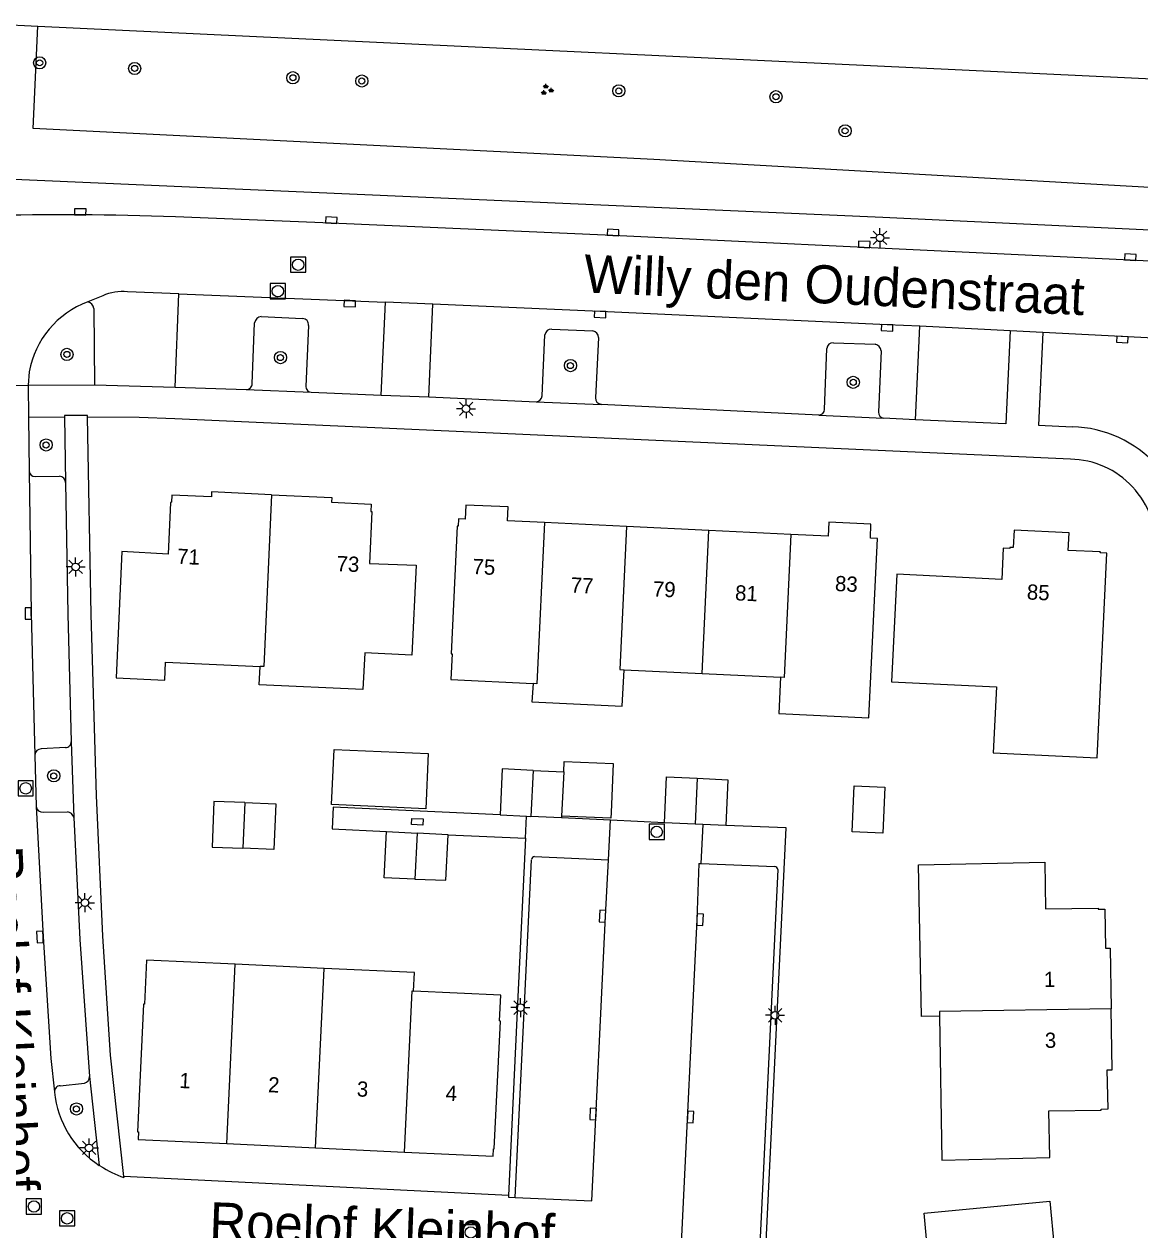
# Model space of a CAD drawing. Extents: x 132994 to 136000, y 393499 to 395512.
# Drawn here: x 133042.5 to 133115.7, y 394512.1 to 394591.2 of the extents above; entities that cross this region are included whole.
import ezdxf

# ---------------------------------------------------------------- set-up
doc = ezdxf.new("R2010")
doc.units = 0
for name, color, linetype in [('gg-afsc-hekwerk', 7, 'Continuous'), ('gg-anno-huisnummerreeks BGT', 7, 'Continuous'), ('gg-anno-openbare ruimte label', 7, 'Continuous'), ('gg-bbg-bijgebouw', 7, 'Continuous'), ('gg-bbg-hoofdgebouw', 7, 'Continuous'), ('gg-bbg-luifel en loopbrug', 7, 'Continuous'), ('gg-bbg-tussenscheiding', 7, 'Continuous'), ('gg-knt-verharding', 7, 'Continuous'), ('gg-knt-verharding nz', 7, 'Continuous'), ('gt-grn-groengrens', 7, 'Continuous'), ('gt-grn-weggrens', 7, 'Continuous'), ('gt-symb-boom', 7, 'Continuous'), ('gt-symb-groenvak', 7, 'Continuous'), ('gt-symb-kolk', 7, 'Continuous'), ('gt-symb-kolk center center', 7, 'Continuous'), ('gt-symb-lichtmast', 7, 'Continuous'), ('gt-symb-rioolschacht', 7, 'Continuous')]:
    doc.layers.add(name, color=color, linetype=linetype)

# ---------------------------------------------------------------- blocks, each defined once
blk = doc.blocks.new('gt0-BOOM')
at = {"layer": 'gt-symb-boom'}
for radius in [0.4, 0.2]:
    blk.add_circle((0, 0), radius, dxfattribs=at)
blk = doc.blocks.new('gt0-LMAST')
at = {"layer": 'gt-symb-lichtmast'}
for p, q in [((-0.182, 0.173), (-0.447, 0.438)), ((-0.005, 0.246), (-0.005, 0.621)), ((0.172, 0.173), (0.437, 0.438)), ((-0.255, -0.004), (-0.63, -0.004)), ((-0.182, -0.181), (-0.447, -0.446)), ((-0.005, -0.254), (-0.005, -0.629)), ((0.437, -0.446), (0.172, -0.181)), ((0.245, -0.004), (0.62, -0.004))]:
    blk.add_line(p, q, dxfattribs=at)
blk.add_circle((-0.005, -0.004), 0.25, dxfattribs=at)
blk = doc.blocks.new('gt0-KOLKCC')
at = {"layer": 'gt-symb-kolk center center'}
blk.add_lwpolyline([(-0.375, 0.2), (0.375, 0.2), (0.375, -0.2), (-0.375, -0.2)], close=True, dxfattribs=at)
blk = doc.blocks.new('gt0-KOLK')
at = {"layer": 'gt-symb-kolk'}
blk.add_lwpolyline([(0, 0), (0.375, 0), (0.375, 0.4), (-0.375, 0.4), (-0.375, 0), (0, 0)], dxfattribs=at)
blk = doc.blocks.new('gt0-RS')
at = {"layer": 'gt-symb-rioolschacht'}
blk.add_lwpolyline([(-0.5, -0.5), (0.5, -0.5), (0.5, 0.5), (-0.5, 0.5)], close=True, dxfattribs=at)
blk.add_circle((0, 0), 0.375, dxfattribs=at)
blk = doc.blocks.new('gt0-GRVAK')
at = {"layer": 'gt-symb-groenvak'}
for p, q in [((-0.11, 0.189), (-0.228, 0.24)), ((-0.182, 0.153), (0.088, 0.153)), ((-0.091, 0.211), (-0.156, 0.322)), ((-0.047, 0.214), (-0.047, 0.393)), ((-0.004, 0.211), (0.061, 0.322)), ((0.015, 0.189), (0.133, 0.24)), ((0.262, -0.052), (0.197, 0.059)), ((0.305, -0.049), (0.305, 0.13)), ((0.349, -0.052), (0.414, 0.059)), ((-0.245, -0.228), (-0.363, -0.177)), ((-0.318, -0.264), (-0.047, -0.264)), ((-0.226, -0.206), (-0.291, -0.095)), ((-0.183, -0.203), (-0.183, -0.024)), ((-0.139, -0.206), (-0.074, -0.095)), ((-0.12, -0.228), (-0.002, -0.177)), ((0.243, -0.074), (0.125, -0.023)), ((0.17, -0.11), (0.441, -0.11)), ((0.368, -0.074), (0.486, -0.023))]:
    blk.add_line(p, q, dxfattribs=at)

msp = doc.modelspace()

# ---------------------------------------------------------------- linework, layer by layer
at = {"layer": 'gg-afsc-hekwerk'}
for p, q in [((133040.64, 394591.221), (133043.422, 394591.089)), ((133043.422, 394591.089), (133124.891, 394587.234)), ((133080.997, 394538.954), (133077.791, 394539.109)), ((133084.542, 394538.783), (133080.997, 394538.954)), ((133070.341, 394538.004), (133075.419, 394537.769)), ((133075.419, 394537.769), (133074.923, 394527.362))]:
    msp.add_line(p, q, dxfattribs=at)
for points in [[(133073.754, 394539.304), (133062.812, 394539.814), (133062.74, 394538.389), (133066.303, 394538.209)], [(133091.083, 394508.56), (133092.539, 394538.454), (133088.577, 394538.6)]]:
    msp.add_lwpolyline(points, dxfattribs=at)
at = {"layer": 'gg-bbg-bijgebouw'}
for p, q in [((133075.919, 394542.223), (133077.937, 394542.125)), ((133077.937, 394542.125), (133077.797, 394539.227)), ((133073.754, 394539.304), (133075.488, 394539.221)), ((133075.488, 394539.221), (133075.772, 394539.207)), ((133077.791, 394539.109), (133075.772, 394539.207)), ((133077.797, 394539.227), (133077.791, 394539.109)), ((133086.559, 394538.692), (133084.542, 394538.783)), ((133087.068, 394538.669), (133086.559, 394538.692)), ((133088.577, 394538.6), (133087.068, 394538.669)), ((133066.303, 394538.209), (133068.322, 394538.107)), ((133070.341, 394538.004), (133068.322, 394538.107))]:
    msp.add_line(p, q, dxfattribs=at)
for points in [[(133075.919, 394542.223), (133073.9, 394542.32), (133073.754, 394539.304)], [(133084.542, 394538.783), (133084.679, 394541.799), (133086.696, 394541.708)], [(133086.696, 394541.708), (133088.714, 394541.616), (133088.577, 394538.6)], [(133098.877, 394538.094), (133096.857, 394538.189), (133096.998, 394541.216), (133099.019, 394541.121), (133098.877, 394538.094)], [(133057.007, 394540.11), (133054.968, 394540.185), (133054.857, 394537.191), (133056.88, 394537.116)], [(133057.007, 394540.11), (133059.046, 394540.034), (133058.903, 394537.041), (133056.88, 394537.116)], [(133068.169, 394535.091), (133066.149, 394535.17), (133066.303, 394538.209)], [(133068.169, 394535.091), (133070.189, 394535.012), (133070.341, 394538.004)]]:
    msp.add_lwpolyline(points, dxfattribs=at)
at = {"layer": 'gg-bbg-hoofdgebouw'}
for p, q in [((133082.061, 394558.237), (133076.667, 394558.493)), ((133087.454, 394557.98), (133082.061, 394558.237)), ((133092.848, 394557.724), (133087.454, 394557.98)), ((133081.894, 394548.838), (133087.01, 394548.59)), ((133087.01, 394548.59), (133092.163, 394548.341)), ((133062.208, 394529.225), (133056.381, 394529.499)), ((133055.821, 394517.725), (133061.647, 394517.448)), ((133061.647, 394517.448), (133067.474, 394517.17))]:
    msp.add_line(p, q, dxfattribs=at)
for points in [[(133058.756, 394560.328), (133054.825, 394560.505), (133054.816, 394560.193), (133052.218, 394560.306), (133052.194, 394559.827), (133052.131, 394559.824), (133051.969, 394556.43), (133048.926, 394556.59), (133048.552, 394548.313), (133051.746, 394548.146), (133051.804, 394549.333), (133058.009, 394549.055)], [(133058.756, 394560.328), (133062.719, 394560.149), (133062.699, 394559.834), (133065.304, 394559.709), (133065.281, 394559.225), (133065.344, 394559.22), (133065.194, 394555.812), (133068.242, 394555.694), (133067.974, 394549.794), (133064.876, 394549.94), (133064.759, 394547.537), (133057.954, 394547.844), (133058.009, 394549.055)], [(133076.667, 394558.493), (133074.248, 394558.608), (133074.287, 394559.524), (133071.517, 394559.643), (133071.473, 394558.721), (133071.031, 394558.751), (133071.008, 394558.265), (133070.938, 394558.268), (133070.544, 394549.875), (133070.606, 394549.87), (133070.522, 394548.185), (133075.923, 394547.925)], [(133097.954, 394545.667), (133098.519, 394557.445), (133098.06, 394557.469), (133098.097, 394558.396), (133095.324, 394558.528), (133095.28, 394557.608), (133092.848, 394557.724)], [(133099.456, 394548.043), (133106.333, 394547.703), (133106.12, 394543.372), (133112.936, 394543.047), (133113.581, 394556.493), (133113.149, 394556.514), (133113.152, 394556.574), (133111.047, 394556.67), (133111.101, 394557.824), (133107.496, 394557.993), (133107.436, 394556.852), (133107.211, 394556.864), (133107.207, 394556.796), (133106.778, 394556.813), (133106.682, 394554.765), (133099.792, 394555.101), (133099.456, 394548.043)], [(133075.923, 394547.925), (133075.849, 394546.73), (133081.776, 394546.438), (133081.894, 394548.838)], [(133092.163, 394548.341), (133092.041, 394545.967), (133097.954, 394545.667)], [(133102.604, 394526.086), (133101.406, 394526.079), (133101.218, 394536.032), (133109.506, 394536.203), (133109.547, 394533.137), (133113.015, 394533.171), (133113.016, 394533.111), (133113.456, 394533.115), (133113.481, 394530.56), (133113.805, 394530.565), (133113.867, 394526.569)], [(133056.381, 394529.499), (133050.558, 394529.772), (133050.421, 394526.879), (133050.358, 394526.879), (133049.958, 394518.498), (133050.02, 394518.495), (133049.994, 394518.002), (133055.821, 394517.725)], [(133068.073, 394527.738), (133068.13, 394528.947), (133062.208, 394529.225)], [(133067.474, 394517.17), (133073.301, 394516.893), (133073.321, 394517.383), (133073.378, 394517.38), (133073.785, 394525.767), (133073.728, 394525.78), (133073.796, 394527.464), (133068.073, 394527.738)], [(133102.604, 394526.086), (133102.755, 394516.647), (133109.84, 394516.801), (133109.765, 394519.867), (133113.216, 394519.928), (133113.215, 394519.988), (133113.655, 394519.996), (133113.609, 394522.568), (133113.929, 394522.573), (133113.867, 394526.569)], [(133102.452, 394503.775), (133101.59, 394513.164), (133109.841, 394513.947), (133110.125, 394510.923), (133113.553, 394511.195), (133113.558, 394511.135), (133113.99, 394511.169), (133114.237, 394508.634), (133114.548, 394508.66), (133114.847, 394504.714)]]:
    msp.add_lwpolyline(points, dxfattribs=at)
at = {"layer": 'gg-bbg-luifel en loopbrug'}
for points in [[(133062.697, 394539.982), (133062.861, 394543.605), (133069.043, 394543.326), (133068.879, 394539.704), (133062.697, 394539.982)], [(133077.937, 394542.125), (133077.968, 394542.813), (133081.183, 394542.668), (133081.038, 394539.452), (133081.021, 394539.081), (133077.797, 394539.227)]]:
    msp.add_lwpolyline(points, dxfattribs=at)
at = {"layer": 'gg-bbg-tussenscheiding'}
for p, q in [((133087.01, 394548.59), (133087.454, 394557.98)), ((133075.919, 394542.223), (133075.772, 394539.207)), ((133086.696, 394541.708), (133086.559, 394538.692)), ((133057.007, 394540.11), (133056.88, 394537.116)), ((133068.322, 394538.107), (133068.169, 394535.091)), ((133055.821, 394517.725), (133056.381, 394529.499)), ((133061.647, 394517.448), (133062.208, 394529.225))]:
    msp.add_line(p, q, dxfattribs=at)
for points in [[(133058.756, 394560.328), (133058.244, 394549.044), (133058.009, 394549.055)], [(133076.667, 394558.493), (133076.166, 394547.914), (133075.923, 394547.925)], [(133082.061, 394558.237), (133081.616, 394548.851), (133081.894, 394548.838)], [(133092.848, 394557.724), (133092.404, 394548.33), (133092.163, 394548.341)], [(133067.474, 394517.17), (133067.977, 394527.743), (133068.073, 394527.738)], [(133113.867, 394526.569), (133102.599, 394526.394), (133102.604, 394526.086)]]:
    msp.add_lwpolyline(points, dxfattribs=at)
at = {"layer": 'gg-knt-verharding'}
for p, q in [((133047.105, 394572.541), (133047.133, 394567.545)), ((133058.083, 394572.018), (133060.795, 394571.893)), ((133057.487, 394567.615), (133057.643, 394571.612)), ((133061.183, 394571.438), (133061.004, 394567.435)), ((133077.151, 394571.197), (133079.841, 394571.074)), ((133109.377, 394570.984), (133107.239, 394571.092)), ((133076.52, 394566.817), (133076.703, 394570.824)), ((133080.207, 394570.641), (133080.025, 394566.685)), ((133095.631, 394570.303), (133098.367, 394570.202)), ((133119.093, 394570.489), (133109.377, 394570.984)), ((133095.058, 394565.927), (133095.194, 394569.934)), ((133098.766, 394569.772), (133098.585, 394565.751)), ((133042.86, 394568.386), (133042.78, 394567.522)), ((133042.78, 394567.522), (133047.133, 394567.545)), ((133042.78, 394567.522), (133042.803, 394565.416)), ((133047.133, 394567.545), (133052.432, 394567.393)), ((133052.432, 394567.393), (133057.094, 394567.228)), ((133057.094, 394567.228), (133061.368, 394567.051)), ((133061.368, 394567.051), (133065.963, 394566.86)), ((133065.963, 394566.86), (133069.073, 394566.754)), ((133069.073, 394566.754), (133076.119, 394566.432)), ((133076.119, 394566.432), (133080.38, 394566.258)), ((133094.67, 394565.558), (133080.38, 394566.258)), ((133094.67, 394565.558), (133098.916, 394565.358)), ((133042.803, 394565.416), (133045.176, 394565.428)), ((133042.803, 394565.416), (133042.846, 394561.87)), ((133045.176, 394565.428), (133045.238, 394561.121)), ((133101.01, 394565.25), (133098.916, 394565.358)), ((133043.247, 394561.52), (133044.842, 394561.544)), ((133045.616, 394544.111), (133045.774, 394539.134)), ((133045.234, 394543.726), (133043.646, 394543.637)), ((133043.231, 394543.235), (133043.303, 394539.86)), ((133043.777, 394539.473), (133045.363, 394539.505)), ((133074.738, 394514.19), (133075.821, 394536.365)), ((133076.019, 394536.566), (133080.871, 394536.348)), ((133086.809, 394536.118), (133086.939, 394536.113)), ((133086.939, 394536.113), (133091.792, 394535.919)), ((133091.98, 394535.722), (133090.794, 394511.096)), ((133074.923, 394527.362), (133074.305, 394514.325)), ((133046.803, 394522.126), (133047.455, 394516.297)), ((133044.886, 394521.522), (133046.476, 394521.697)), ((133047.542, 394516.242), (133047.455, 394516.297)), ((133074.305, 394514.325), (133049.062, 394515.569))]:
    msp.add_line(p, q, dxfattribs=at)
for points in [[(133000.84, 394582.282), (133008.833, 394582.314), (133014.845, 394582.146), (133022.858, 394581.865), (133098.874, 394578.557), (133182.516, 394574.595)], [(133119.344, 394575.497), (133115.103, 394575.72), (133097.644, 394576.559), (133081.165, 394577.337), (133062.671, 394578.155), (133052.445, 394578.565)], [(133107.239, 394571.092), (133106.941, 394564.978), (133101.01, 394565.25)], [(133109.377, 394570.984), (133109.101, 394564.895), (133111.325, 394564.791)], [(133046.676, 394565.409), (133046.676, 394565.524), (133045.177, 394565.526), (133045.176, 394565.428)], [(133111.193, 394562.657), (133052.415, 394565.305), (133050.071, 394565.396), (133046.676, 394565.409)], [(133049.062, 394515.569), (133048.19, 394523.532), (133047.687, 394531.332), (133047.262, 394540.581), (133046.91, 394552.47), (133046.676, 394565.409)], [(133045.238, 394561.121), (133045.398, 394552.478), (133045.616, 394544.111)], [(133045.774, 394539.134), (133046.17, 394531.129), (133046.803, 394522.126)], [(133074.305, 394514.325), (133074.299, 394514.199), (133074.738, 394514.19)]]:
    msp.add_lwpolyline(points, dxfattribs=at)
for centre, radius, start, end in [((133044.971, 394371.221), 207.479, 87.93568, 91.3854), ((133048.759, 394567.364), 5.987, 110.19838, 170.17331), ((133046.588, 394572.472), 0.521, 7.60664, 78.50812), ((133058.114, 394571.543), 0.476, 93.68455, 171.71259), ((133060.789, 394571.495), 0.398, 351.80749, 89.1041), ((133077.116, 394570.784), 0.415, 85.12234, 174.43846), ((133079.793, 394570.662), 0.415, 357.1034, 83.30997), ((133095.613, 394569.881), 0.423, 87.59221, 172.76285), ((133098.305, 394569.745), 0.462, 3.40842, 82.30848), ((133057.103, 394567.612), 0.384, 268.69355, 0.425), ((133061.389, 394567.435), 0.385, 180.00062, 266.93616), ((133076.096, 394566.857), 0.426, 273.0831, 354.58457), ((133080.418, 394566.651), 0.394, 174.99794, 264.4811), ((133094.676, 394565.941), 0.383, 269.14848, 357.97598), ((133098.957, 394565.728), 0.372, 176.45764, 263.75315), ((133111.079, 394556.926), 7.869, 356.86028, 88.20813), ((133111.097, 394556.965), 5.693, 356.61691, 89.03435), ((133043.228, 394561.903), 0.384, 185.00433, 272.76559), ((133044.791, 394561.099), 0.448, 2.77867, 83.44495), ((133045.234, 394544.108), 0.382, 270.05877, 0.38943), ((133043.641, 394543.227), 0.41, 89.2452, 178.93158), ((133043.755, 394539.93), 0.457, 188.78565, 272.75412), ((133045.323, 394539.047), 0.459, 10.86472, 84.99164), ((133076.032, 394536.356), 0.211, 93.43238, 177.4292), ((133091.765, 394535.705), 0.215, 4.42396, 82.89777), ((133046.405, 394522.09), 0.399, 280.17715, 5.19081), ((133044.893, 394521.147), 0.375, 91.02328, 185.31187), ((133050.964, 394521.739), 6.476, 185.56031, 237.18612)]:
    msp.add_arc(centre, radius, start, end, dxfattribs=at)
at = {"layer": 'gg-knt-verharding nz'}
for p, q in [((133047.676, 394573.392), (133046.692, 394572.983)), ((133052.673, 394573.517), (133049.296, 394573.65)), ((133052.432, 394567.393), (133052.673, 394573.517)), ((133052.673, 394573.517), (133066.229, 394572.974)), ((133065.963, 394566.86), (133066.229, 394572.974)), ((133069.338, 394572.839), (133066.229, 394572.974)), ((133069.073, 394566.754), (133069.338, 394572.839)), ((133101.01, 394565.25), (133101.308, 394571.381)), ((133107.239, 394571.092), (133101.308, 394571.381)), ((133080.871, 394536.348), (133080.997, 394538.954)), ((133087.068, 394538.669), (133086.939, 394536.113)), ((133049.062, 394515.569), (133049.069, 394515.502))]:
    msp.add_line(p, q, dxfattribs=at)
for points in [[(133101.308, 394571.381), (133099.167, 394571.486), (133080.331, 394572.36), (133069.338, 394572.839)], [(133042.846, 394561.87), (133042.988, 394552.534), (133043.231, 394543.235)], [(133043.303, 394539.86), (133043.759, 394531.293), (133044.274, 394523.316), (133044.519, 394521.112)], [(133074.738, 394514.19), (133079.789, 394513.958), (133080.679, 394532.647), (133080.871, 394536.348)], [(133086.809, 394536.118), (133086.68, 394532.441), (133085.652, 394511.16)]]:
    msp.add_lwpolyline(points, dxfattribs=at)
for centre, radius, start, end in [((133048.964, 394570.517), 3.15, 83.95623, 114.14155), ((133050.961, 394521.352), 6.149, 236.21362, 252.07577)]:
    msp.add_arc(centre, radius, start, end, dxfattribs=at)
at = {"layer": 'gt-grn-groengrens'}
msp.add_line((133043.103, 394584.359), (133043.422, 394591.089), dxfattribs=at)
msp.add_lwpolyline([(133124.891, 394587.234), (133124.545, 394580.037), (133083.855, 394582.336), (133043.103, 394584.359)], dxfattribs=at)
at = {"layer": 'gt-grn-weggrens'}
for p, q in [((133037.827, 394567.391), (133042.78, 394567.522)), ((133075.419, 394537.769), (133075.488, 394539.221))]:
    msp.add_line(p, q, dxfattribs=at)

# ---------------------------------------------------------------- block references
at = {"layer": 'gt-symb-boom'}
for p in [(133043.54, 394588.679), (133049.774, 394588.309), (133060.161, 394587.7), (133064.682, 394587.486), (133081.549, 394586.836), (133091.864, 394586.454), (133096.399, 394584.214), (133045.33, 394569.536), (133059.342, 394569.327), (133078.376, 394568.801), (133096.936, 394567.704), (133043.963, 394563.592), (133044.463, 394541.865), (133045.952, 394519.999)]:
    msp.add_blockref('gt0-BOOM', p, dxfattribs=at)
at = {"layer": 'gt-symb-groenvak'}
msp.add_blockref('gt0-GRVAK', (133076.809, 394586.898), dxfattribs=at)
at = {"layer": 'gt-symb-kolk'}
for p, rotation in [((133046.197, 394578.696), -1.2025665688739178), ((133062.671, 394578.155), -3.003456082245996), ((133081.165, 394577.337), -3.0034560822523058), ((133097.644, 394576.559), -3.0034560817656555), ((133115.103, 394575.72), -3.003456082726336), ((133063.898, 394573.076), 177.74809154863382), ((133080.331, 394572.36), 177.5055394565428), ((133099.167, 394571.486), 177.34393590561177), ((133114.609, 394570.719), 177.09366989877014), ((133042.988, 394552.534), 90.87159696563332), ((133080.679, 394532.647), 87.02072152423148), ((133086.68, 394532.441), -92.76891578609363), ((133043.759, 394531.293), 93.0518080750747), ((133080.061, 394519.659), 87.27944664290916), ((133086.054, 394519.487), -92.76891578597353)]:
    msp.add_blockref('gt0-KOLK', p, dxfattribs=dict(at, rotation=rotation))
at = {"layer": 'gt-symb-kolk center center', "rotation": -2.429615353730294}
msp.add_blockref('gt0-KOLKCC', (133068.331, 394538.854), dxfattribs=at)
at = {"layer": 'gt-symb-lichtmast'}
for p in [(133098.692, 394577.193), (133071.532, 394565.972), (133045.903, 394555.59), (133046.51, 394533.544), (133075.1, 394526.653), (133091.811, 394526.15), (133046.79, 394517.446)]:
    msp.add_blockref('gt0-LMAST', p, dxfattribs=at)
at = {"layer": 'gt-symb-rioolschacht'}
for p in [(133060.502, 394575.425), (133059.176, 394573.692), (133042.622, 394541.05), (133084.037, 394538.188), (133043.163, 394513.595), (133045.339, 394512.816), (133071.84, 394511.895)]:
    msp.add_blockref('gt0-RS', p, dxfattribs=at)

# ---------------------------------------------------------------- texts
at = {"layer": 'gg-anno-huisnummerreeks BGT'}
for s, rotation, p in [('71', 357.5, (133052.545, 394555.787)), ('73', 357.3, (133063.01, 394555.314)), ('75', 357.5, (133071.933, 394555.121)), ('77', 357.3, (133078.374, 394553.907)), ('79', 357.3, (133083.767, 394553.651)), ('81', 357.3, (133089.161, 394553.394)), ('83', 357.3, (133095.72, 394554.005)), ('85', 357.3, (133108.312, 394553.451)), ('1', 0.9, (133109.456, 394527.999)), ('3', 0.9, (133109.518, 394524.003)), ('1', 357.3, (133052.685, 394521.378)), ('2', 357.3, (133058.512, 394521.101)), ('3', 357.3, (133064.339, 394520.823)), ('4', 357.3, (133070.165, 394520.546))]:
    msp.add_text(s, height=1, rotation=rotation, dxfattribs=at).set_placement(p)
at = {"layer": 'gg-anno-openbare ruimte label'}
for s, rotation, p in [('Willy den Oudenstraat', 357.4, (133079.208, 394573.605)), ('Roelof Kleinhof', 272.8, (133039.903, 394537.209)), ('Roelof Kleinhof', 357.9, (133054.643, 394511.384))]:
    msp.add_text(s, height=2.5, rotation=rotation, dxfattribs=at).set_placement(p)

doc.saveas('drawing.dxf')
